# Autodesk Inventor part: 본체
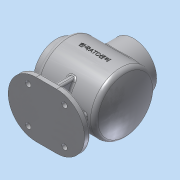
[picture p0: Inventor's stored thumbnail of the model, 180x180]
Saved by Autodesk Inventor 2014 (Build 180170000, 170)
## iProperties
Created: 2023-01
Part Number: 본체
Material: 알루미늄 6061
Document SubType Name: Modeling
Designer: dg
Density: 2.71 g/cm^3
Appearance: 알루미늄 - 평지
Mass: 1038.22 g
Surface Area: 1157.5 cm^2
Volume: 383.109 cm^3
Author: dg
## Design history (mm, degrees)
sketch "스케치1"
  geometry: L1 (0, 0)-(122, 0); L2 (0, 0)-(0, 38); L3 (0, 38)-(12, 38); L4 (12, 38)-(12, 50); L5 (12, 50)-(111.087, 50); L6 (107.83, 45)-(17, 45); L7 (17, 45)-(17, 27); L8 (17, 27)-(0, 27); A1 r 120 centre (2, 0) between (122, 0) and (111.087, 50); A2 r 115 centre (2, 0) between (117, 0) and (107.83, 45)
  constraints: 16 end point, 4 point on circle, 2 centre point, 2 horizontal, 2 perpendicular, 2 point on line, 1 horizontal alignment, 1 parallel, 1 other
  dimensions: "d0" = 122 distance of L1.start L1.end; "d1" = 110 distance from line of L1.end L4; "d2" = 76 diameter of L3 L1; "d3" = 100 diameter of L5 L1; "d4" = 120 radius of A1; "d5" = 54 diameter of L8 L1; "d6" = 5 radial gap between concentric circles of A1 A2; "d7" = 90 diameter of L6 L1
revolve "회전1" sketch "스케치1" stored, may be unused: angle "d8" = 90 deg
node "작업 평면1"
sketch "스케치2"
  geometry: L1 (-46, 0)-(-80, 0); L2 (-46, 46)-(-80, 46); L3 (-80, -46)-(-46, -46); A1 r 46 centre (-46, 0) between (-46, -46) and (-46, 46); A2 r 46 centre (-80, 0) between (-80, 46) and (-80, -46); 4 further points
  constraints: 8 end point, 6 point on circle, 4 tangent, 2 centre point, 2 coincident, 1 horizontal, 1 horizontal alignment, 1 midpoint, 1 parallel
  dimensions: "d10" = 126 distance of point (-126, 0) point (0, 0); "d11" = 92 distance between parallel lines of L3 L2
extrude "돌출1" join sketch "스케치2" distance "d12" = 10; taper "d13" = 0 deg
node "작업 평면2"
sketch "스케치3"
  geometry: L1 (-80, 46)-(-70, 46) reference; L2 (-70, 46)-(-70, -46) reference; L3 (-70, -46)-(-80, -46) reference; L4 (-80, -46)-(-80, 46) reference; L5 (-35.707, 35)-(-70, 35); L6 (-35.707, -35)-(-70, -35); C1 r 45 at (0, 0) reference; A1 r 50 centre (0, 0) between (-35.707, 35) and (-35.707, -35) reference; 1 further point
  constraints: 4 end point, 2 perpendicular, 2 point on circle, 2 point on line, 1 parallel
  dimensions: "d15" = 70 distance between parallel lines of L6 L5
extrude "돌출2" join sketch "스케치3" stored distance "d16" = 10; taper "d17" = 0 deg
node "작업 평면3"
sketch "스케치4"
  geometry: L1 (107.83, 45)-(17, 45) reference; L2 (17, 45)-(17, 27) reference; L3 (17, 27)-(0, 27) reference; L4 (0, 27)-(0, 38) reference; L5 (0, 38)-(12, 38) reference; L6 (12, 38)-(12, 50) reference; L7 (12, 50)-(111.087, 50) reference; L8 (111.087, -50)-(68, -50) reference; L9 (68, -50)-(68, -70) reference; L10 (68, -70)-(126, -70) reference; L11 (126, -70)-(126, -80) reference; L12 (126, -80)-(0, -80) reference; L13 (0, -80)-(0, -70) reference; L14 (0, -70)-(58, -70) reference; L15 (58, -70)-(58, -50) reference; L16 (58, -50)-(12, -50) reference; L17 (12, -50)-(12, -38) reference; L18 (12, -38)-(0, -38) reference; L19 (0, -38)-(0, -27) reference; L20 (0, -27)-(17, -27) reference; L21 (17, -27)-(17, -45) reference; L22 (17, -45)-(107.83, -45) reference; L23 (28.359, -50)-(23, -70); L24 (97.641, -50)-(103, -70); A1 r 115 centre (2, 0) between (107.83, -45) and (107.83, 45) reference; A2 r 120 centre (2, 0) between (111.087, -50) and (111.087, 50) reference; 1 further point
  constraints: 4 end point, 4 point on line, 1 equal length
  dimensions: "d19" = 23 distance from line of L13 L23.end; "d20" = 105 deg angle of L14 L23; "d21" = 80 distance of L24.end L23.end
  node "절단 모서리 투영2"
feature "리브1" dims "d22" = 1, "d23" = 10, "d24" = 0, "d25" = 0, "d26" = 1, "d27" = 1
feature "리브2" dims "d28" = 1, "d29" = 10, "d30" = 0, "d31" = 0, "d32" = 1, "d33" = 1
node "작업 평면4"
sketch "스케치5"
  geometry: L1 (-12, 50)-(-12, -50) reference; C1 r 38 at (-63, 0); 1 further point
  constraints: 1 centre point, 1 horizontal alignment
  dimensions: "d35" = 51 distance from line of L1 C1.centre; "d36" = 76 diameter of C1
extrude "돌출3" join sketch "스케치5" stored distance "d37" = 10; taper "d38" = 0 deg
sketch "스케치6"
  geometry: C1 r 38 at (0, 0) reference; 2 further points
  constraints: 1 coincident
hole "구멍1" sketch "스케치6" at (0, 0) diameter "d39" = 54; stored, may be unused: countersink angle "d43" = 90 deg, drill point angle "d45" = 118 deg; dims "d40" = 6, "d41" = 4, "d42" = 2, "d44" = 8
sketch "스케치7"
  geometry: C1 r 38 at (0, 0) reference; 1 further point
  constraints: 1 vertical alignment
  dimensions: "d46" = 32.5 distance of C1.centre point (0, 32.5)
hole "구멍2" sketch "스케치7" at (0, 32.5) diameter "d47" = 3.242; stored, may be unused: countersink angle "d51" = 90 deg, drill point angle "d53" = 118 deg; dims "d48" = 8, "d49" = 4, "d50" = 2, "d52" = 10
sketch "스케치8"
  geometry: C1 r 27 at (0, 0) reference; 2 further points
  constraints: 1 vertical alignment
  dimensions: "d57" = 32.5 distance of C1.centre point (0, 32.5)
hole "구멍3" sketch "스케치8" at (0, 32.5) diameter "d58" = 3.242; stored, may be unused: countersink angle "d62" = 90 deg, drill point angle "d64" = 118 deg; dims "d59" = 8, "d60" = 4, "d61" = 2, "d63" = 10
sketch "스케치9"
  geometry: L1 (58, -5)-(23, -5) reference; L2 (58, 5)-(58, 35) reference; 5 further points
  constraints: 2 horizontal alignment, 2 vertical alignment
  dimensions: "d68" = 60 distance of point (93, 30) point (33, 30); "d69" = 60 distance of point (33, 30) point (33, -30); "d70" = 25 distance from line of L2 point (33, 30); "d71" = 25 distance from line of L1 point (33, -30)
hole "구멍4" sketch "스케치9" at (33, 30), (93, 30), (93, -30), (33, -30) diameter "d72" = 9; stored, may be unused: countersink angle "d76" = 90 deg, drill point angle "d78" = 118 deg; dims "d73" = 8, "d74" = 4, "d75" = 2, "d77" = 10
fillet "모깎기1" dims "d79" = 8
fillet "모깎기2" dims "d80" = 3
fillet "모깎기3" dims "d81" = 3
chamfer "모따기1" distance "d82" = 1; stored, may be unused: second distance "d83" = 2, angle "d84" = 45 deg
fillet "모깎기4" dims "d85" = 3
fillet "모깎기5" dims "d86" = 3
node "작업 평면5"
sketch "스케치10"
  geometry: L1 (-41.544, 0)-(44.283, 0) reference; L2 (-61.544, -38)-(-61.544, 38) reference; L3 (64.456, -80)-(18.456, -80) reference; 2 further points
  constraints: 1 other
  dimensions: "d87" = 63 distance from line of L2 point (1.456, 0); "d88" = 80 distance from line of L3 point (1.456, 0)
feature "엠보싱1" sketch "스케치10" dims "d89" = 0.5, "d90" = 0
node "솔리드1"
pattern_circular "원형 패턴1" dims angle "d55" = 360 deg
pattern_circular "원형 패턴2" dims angle "d66" = 360 deg
node "절단 모서리 투영1"
node "절단 모서리 투영3"
other parameters: "d14" = 63, "d18" = 0, "d34" = 144
